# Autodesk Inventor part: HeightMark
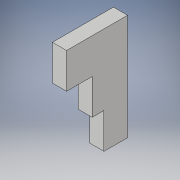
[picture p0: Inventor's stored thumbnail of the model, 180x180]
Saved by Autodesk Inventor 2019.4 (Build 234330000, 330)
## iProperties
Created: 2019-11
Part Number: HeightMark
Material: Všeobecné
Document SubType Name: Modeling
Designer: navara
Mass: 572222 g
Surface Area: 59407.4 cm^2
Volume: 572222 cm^3
Density: 1 g/cm^3
Appearance: Výchozí
Author: navara
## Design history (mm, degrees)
sketch "Náčrt1"
  geometry: L1 (0, 0)-(0, 500); L2 (0, 500)-(750, 500); L3 (750, 500)-(750, 750); L4 (750, 750)-(1500, 750); L5 (1500, 750)-(1500, 1293.21); L6 (1500, 1293.21)-(2250, 1293.21); L7 (2250, 1293.21)-(2250, 0); L8 (2250, 0)-(0, 0)
  constraints: 16 end point, 6 perpendicular, 1 horizontal, 1 vertical
  dimensions: "d0" = 500 distance of L1.start L1.end; "d1" = 750 distance of L1.end L2.end; "d2" = 250 distance of L2.end L3.end; "d3" = 750 distance of L3.end L4.end; "d4" = 543.21 distance of L4.end L5.end; "d5" = 750 distance of L5.end L6.end
extrude "Vysunutí1" new body sketch "Náčrt1" distance "d6" = 300; taper "d7" = 0 deg
node "Těleso1"
